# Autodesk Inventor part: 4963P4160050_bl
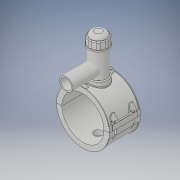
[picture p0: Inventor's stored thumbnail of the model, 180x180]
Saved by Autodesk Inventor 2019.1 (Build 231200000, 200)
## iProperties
Created: 2017-07
Part Number: 4963P4160050_bl
Material: Generic
Document SubType Name: Modeling
Designer: KIM
Density: 1 g/cm^3
Appearance: Default
Author: KIM
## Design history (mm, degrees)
derived "4963P4.ipt"
feature "Solid1::4963P4.ipt" dims "ScaleForDerivedMember" = 10
feature "Solid2::4963P4.ipt" dims "ScaleForDerivedMember" = 10
feature "Solid3::4963P4.ipt" dims "ScaleForDerivedMember" = 10
tag "TaggingFeature1"
body "Solid1"
body "Solid2"
body "Solid3"
other parameters: "d2" = 199 [user parameter], "d4" = 118 [user parameter], "d5" = 0 [user parameter], "d6" = 0.1 [user parameter], "d8" = 0 [user parameter], "d19" = 6 [user parameter], "d20" = 6 [user parameter], "d21" = 70.8 [user parameter], "d23" = 0 [user parameter], "d24" = 35.4 [user parameter], "d26" = 0 [user parameter], "d27" = 3 [user parameter], "d28" = 3 [user parameter], "d29" = 3 [user parameter], "d30" = 53.33333 [user parameter], "d31" = 6 [user parameter], "d32" = 0 [user parameter], "d33" = 0 [user parameter], "d34" = 0.6 [user parameter], "d40" = 101.504 [user parameter], "d41" = 72 [user parameter], "d43" = 0 [user parameter], "d45" = 0 [user parameter], "d47" = 168.4 [user parameter], "d70" = 15 [user parameter], "d72" = 0 [user parameter], "d73" = 6 [user parameter], "d75" = 5 [user parameter], "d76" = 0 [user parameter], "d77" = 8 [user parameter], "d79" = 15 [user parameter], "d80" = 47.2 [user parameter], "d82" = 5 deg [user parameter], "d84" = 4 [user parameter], "d85" = 14 [user parameter], "d86" = 0 [user parameter], "d87" = 3 [user parameter], "d88" = 0 [user parameter], "d89" = 1 [user parameter], "d90" = 1 [user parameter], "d91" = 94.4 [user parameter], "d92" = 0 [user parameter], "d93" = 0.5 [user parameter], "d94" = 84.21053 [user parameter], "d96" = 199.104 [user parameter], "d97" = 2.36 [user parameter], "d98" = 0 [user parameter], "d102" = 1.6 [user parameter], "d120" = 140 deg [user parameter], "d121" = 24.228 [user parameter], "d122" = 20 deg [user parameter], "d123" = 390.4 [user parameter], "d124" = 117.12 [user parameter], "d126" = 0 [user parameter], "d143" = 164.8 [user parameter], "d145" = 27.07692 [user parameter], "d149" = 2.4 [user parameter], "d150" = 29.78462 [user parameter], "d153" = 118 [user parameter], "d154" = 0 [user parameter], "d156" = 97.6 [user parameter], "d157" = 160 deg [user parameter], "d159" = 7.04 [user parameter], "d161" = 2.4 [user parameter], "d162" = 70.8 [user parameter], "d163" = 0 [user parameter], "d167" = 16 [user parameter], "d168" = 95.21951 [user parameter], "d170" = 3.75 [user parameter], "d172" = 0 [user parameter], "d173" = 1 [user parameter], "d176" = 20 deg [user parameter], "d177" = 11.2 [user parameter], "d178" = 35.2 [user parameter], "d180" = 0 [user parameter], "d183" = 14.08 [user parameter], "d184" = 8.96 [user parameter], "d185" = 38.35 [user parameter], "d186" = 38.35 [user parameter], "d187" = 97.6 [user parameter], "d188" = 10.56 [user parameter], "d189" = 11.2 [user parameter], "d190" = 0 [user parameter], "d191" = 146.4 [user parameter], "d193" = 8 [user parameter], "d194" = 4.13 [user parameter], "d195" = 90 deg [user parameter], "d197" = 0 [user parameter], "d199" = 0 [user parameter], "d200" = 17.6 [user parameter], "d202" = 0 [user parameter], "d203" = 177 [user parameter], "d204" = 68.4 [user parameter], "d205" = 50.4 [user parameter], "d206" = 61.2 [user parameter], "d207" = 132.75 [user parameter], "d208" = 138.06 [user parameter], "d209" = 164.61 [user parameter], "d210" = 61.92 [user parameter], "d211" = 72 [user parameter], "d212" = 57.6 [user parameter], "d213" = 35.1 [user parameter], "d216" = 0 [user parameter], "d217" = 16 [user parameter], "d218" = 16 [user parameter], "d219" = 3.2 [user parameter], "d224" = 0 [user parameter], "d225" = 64 [user parameter], "d228" = 123 [user parameter], "d230" = 3.2 [user parameter], "B_" = 199 [user parameter], "L_" = 118 [user parameter], "d_t" = 6 [user parameter], "H_2" = 177 [user parameter], "H_1" = 64 [user parameter], "H_" = 123 [user parameter], "d1" = 195.2 [user parameter], "d148" = 2.4 [user parameter], "d160" = 2.4 [user parameter], "d169" = 3.75 [user parameter]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
